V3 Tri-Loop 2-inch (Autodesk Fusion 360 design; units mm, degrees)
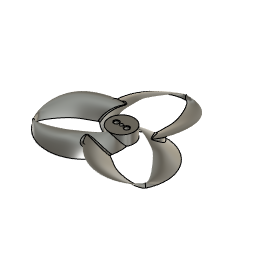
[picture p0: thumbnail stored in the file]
work_plane "WorkPlane9" AlongDistance 2.5
work_plane "WorkPlane10" AlongDistance -2.5
coil_primitive "CoilPrimitive4" Diameter 12 SectionSize 1 TaperAngle 0 Height 38.1 (= "( 25.4 * 1.5 ) * 1 mm")
coil_primitive "CoilPrimitive5" Diameter 25.4 SectionSize 1 TaperAngle 0 Height 38.1 (= "( 25.4 * 1.5 ) * 1 mm")
move "Move1"
sketch "Profile Start" plane through (2.5, 0, 0) normal (1, 0, 0) x axis (0, 1, 0)
  line L1 (-2.2, 0) -> (-3, 0)
  curve K1 (-3, 0) -> (-2.2, 0)
  curve K2 (-4, -1.5) -> (-2, 1.5)
  curve K3 (-1.2, 1.5) -> (-3.2, -1.5)
  curve K4 (1.75, 5) -> (2.25, 5)
  point P2 (-3, 0)
  point P4 (-2.2, 0)
  point P3 (2, 5)
  point P1 (0, 0)
  point P5 (-2, 1.5)
  point P8 (-1.2, 1.5)
  point P9 (2.25, 5)
  point P10 (1.75, 5)
  horizontal L1
  midpoint P2 K2
  midpoint P4 K3
  midpoint P3 K4
  dimension "d65" distance P1 P3 = 2
  dimension "d66" distance P1 P3 = 5
  dimension "d67" distance P1 P2 = 3
  dimension "d68" distance P2 P5 = 1
  dimension "d69" distance P2 P5 = 1.5
  dimension "d70" distance P4 P8 = 1.5
  dimension "d71" distance P5 P8 = 0.8
  dimension "d72" distance P9 P10 = 0.5
  dimension "d134" distance P2 P4 = 0.8
sketch "Profile End" plane through (-2.5, 0, 0) normal (1, 0, 0) x axis (0, 1, 0)
  curve K1 (3, 0) -> (2.2, 0)
  curve K2 (1.5, 1.5) -> (3.3196, -1.2262)
  curve K3 (-1.75, 4.6) -> (-2.25, 4.6)
  curve K4 (4, -1.5) -> (2, 1.5)
  line L1 (-1.75, 4.6) -> (-2.25, 4.6)
  line L2 (2.2, 0) -> (3, 0)
  point P5 (-1.75, 4.6)
  point P9 (-2.25, 4.6)
  point P4 (2.2, 0)
  point P8 (3, 0)
  point P6 (-2, 4.5)
  point P11 (0, 0)
  point P3 (1.5, 1.5)
  point P7 (2, 1.5)
  dimension "d84" distance P5 P9 = 0.5
  dimension "d89" distance P4 P8 = 0.8
  dimension "d101" distance P6 P11 = 4.5
  dimension "d102" distance P6 P11 = 2
  dimension "d103" distance P8 P11 = 3
  dimension "d104" distance P3 P11 = 1.5
  dimension "d105" distance P3 P11 = 1.5
  dimension "d106" distance P7 P11 = 2
  dimension "d107" distance P7 P11 = 1.5
sketch "Target Shape" plane through (0, 0, 0) normal (0, 0, 1) x axis (1, 0, 0)
  circle C1 centre (0, 0) radius 25.4
  circle C2 centre (0, 11.7) radius 13.7
  point P1 (0, 0)
  point P2 (0, 0)
  coincident P1 P2
  tangent C1 C2
  dimension "d95" diameter C1 = 50.8
sketch "Profile Edge" plane through (0, 0, 0) normal (1, 0, 0) x axis (0, 1, 0)
  line L1 (25.4, 0) -> (24.9, 0)
  curve K1 (24.9, 0) -> (25.4, 0)
  curve K2 (25.0501, 1.9961) -> (25.2499, 2.0039)
  curve K3 (25.4, 0.8) -> (25.4, -0.8)
  curve K4 (24.9, -0.8) -> (24.9, 0.8)
  point P4 (25.15, 2)
  point P3 (25.4, 0)
  point P2 (24.9, 0)
  point P1 (0, 0)
  point P5 (25.2499, 2.0039)
  point P6 (25.0501, 1.9961)
  horizontal L1
  midpoint P4 K2
  midpoint P3 K3
  midpoint P2 K4
  dimension "d96" distance P2 P3 = 0.5
  dimension "d98" distance P3 P4 = 2
  dimension "d121" distance P1 P4 = 2
  dimension "d138" distance P5 P6 = 0.2
work_plane "WorkPlane11" AlongDistance 12.7 (= "( 50.8 / 4 ) * 1 mm")
sketch "Profile Mid" plane through (0, 12.7, 0) normal (0, 1, 0) x axis (1, 0, 0)
  line L1 (12.7, 0) -> (13.5, 0)
  curve K1 (12.7, 0) -> (13.5, 0)
  curve K2 (5.25, -4.5) -> (5.75, -4.5)
  curve K3 (14.4, 1.5) -> (11, -1.5)
  curve K4 (11.8, -1.5) -> (15.2, 1.5)
  line L2 (-6.3, 0) -> (-5.5, 0)
  curve K5 (-6.3, 0) -> (-5.5, 0)
  curve K6 (-7.3, -1.5) -> (-3.7, 1.5)
  curve K7 (-13.7, -4.5) -> (-13.3, -4.5)
  curve K8 (-4.3, 1.5) -> (-8.3, -1.5)
  point P3 (5.5, -4.5)
  point P4 (12.7, 0)
  point P2 (13.5, 0)
  point P15 (-13.5, -4.5)
  point P14 (-6.3, 0)
  point P11 (-5.5, 0)
  point P5 (5.75, -4.5)
  point P6 (5.25, -4.5)
  point P1 (0, 0)
  point P18 (-13.7, -4.5)
  point P19 (-13.3, -4.5)
  midpoint P3 K2
  midpoint P4 K3
  midpoint P2 K4
  midpoint P15 K7
  midpoint P14 K8
  midpoint P11 K6
  dimension "d109" distance P2 P4 = 0.8
  dimension "d110" distance P2 P3 = 4.5
  dimension "d111" distance P2 P3 = 8
  dimension "d112" distance P5 P6 = 0.5
  dimension "d113" distance P1 P2 = 13.5
  dimension "d114" distance P11 P14 = 0.8
  dimension "d116" distance P11 P15 = 8
  dimension "d117" distance P18 P19 = 0.4
  dimension "d118" distance P1 P15 = 13.5
  dimension "d187" distance P1 P15 = 4.5
sketch "Lower Rails" plane through (0, 0, 0) normal (0, 0, 1) x axis (1, 0, 0)
  curve K1 (-2.5, 2.2) -> (0, 25.4)
  curve K2 (1, 2) -> (-6, 2.4)
  curve K3 (-6.5029, 7.8529) -> (-6.0971, 17.5471)
  curve K4 (-1.5, 25.4) -> (1.5, 25.4)
  curve K5 (-2.5, 3) -> (0, 24.9)
  curve K6 (1.0379, 2.7978) -> (-6.0379, 3.2022)
  curve K7 (-5.4941, 9.0775) -> (-5.5059, 16.3225)
  curve K8 (-1.5, 24.9) -> (1.5, 24.9)
  arc A1 centre (-1.0067, 11.1418) radius 13.795 clockwise from (0, 24.9) to (2.5, -2.2)
  arc A2 centre (-0.805, 11.0191) radius 14.4034 clockwise from (0, 25.4) to (2.5, -3)
  point P8 (12.7, 12.7)
  point P9 (-6.3, 12.7)
  point P12 (-6.3, 12.7)
  point P10 (-2.5, 2.2)
  point P13 (-2.5, 2.2)
  point P11 (0, 25.4)
  point P5 (0, 24.9)
  point P20 (0, 24.9)
  point P21 (-5.5, 12.7)
  point P23 (-5.5, 12.7)
  point P4 (-2.5, 3)
  point P22 (-2.5, 3)
  point P33 (13.5, 12.7)
  point P30 (0, 25.4)
  point P28 (1.5, 24.9)
  point P29 (-1.5, 24.9)
  point P18 (1.5, 25.4)
  point P19 (-1.5, 25.4)
  coincident P8 A1
  coincident P9 P12
  coincident P10 P13
  midpoint P13 K2
  midpoint P12 K3
  midpoint P11 K4
  coincident P5 P20
  coincident P21 P23
  coincident P4 P22
  midpoint P22 K6
  parallel K2 K6
  midpoint P21 K7
  midpoint P20 K8
  coincident P33 A2
  coincident P11 P30
  dimension "d136" distance P28 P29 = 3
  dimension "d137" distance P18 P19 = 3
work_plane "WorkPlane12" AlongDistance 5
sketch "Upper Rails" plane through (0, 0, 5) normal (0, 0, 1) x axis (1, 0, 0)
  line L1 (0, 25.4) -> (0, 24.9)
  curve K1 (2.5, 2) -> (0, 25.15)
  curve K2 (-0.2, 2) -> (5.2, 2)
  curve K3 (5.51, 10.575) -> (5.4914, 14.825)
  curve K4 (1.5, 25.15) -> (-1.5, 25.15)
  curve K5 (-2.5, -2) -> (0, 25.15)
  curve K6 (3, -2) -> (-8, -2)
  curve K7 (-5, 25.15) -> (5, 25.15)
  curve K8 (-13.6414, 7.825) -> (-13.36, 17.575)
  point P7 (2.5, 2)
  point P9 (2.5, 2)
  point P6 (5.5007, 12.7)
  point P5 (0, 25.15)
  point P18 (-2.5, -2)
  point P16 (0, 25.15)
  point P17 (-13.5007, 12.7)
  point P14 (-1.5, 25.15)
  point P15 (1.5, 25.15)
  coincident P7 P9
  midpoint P7 K2
  midpoint P6 K3
  midpoint P5 K4
  midpoint P18 K6
  midpoint P16 K7
  midpoint P17 K8
  dimension "d135" distance P14 P15 = 3
loft "Loft3" sketch "Profile Start" + "Profile Mid" + "Profile Edge" bodies "Blade Template 2x1.6x3"
loft "Loft4" sketch "Profile Edge" + "Profile Mid" + "Profile End"
circular_pattern "C-Pattern2" TotalAngle 360
combine "Combine2" bodies "Blade Template 2x2.5x3 (1)"
offset_faces "OffsetFaces5" distance -0.5
circular_pattern "C-Pattern3" TotalAngle 360
combine "Combine3"
fillet "Fillet2" radius 1
copy_paste_bodies "CopyPasteBodies6"
move "Move2"
scale "Scale2" ScaleX 1.25 ScaleY 1.25
sketch "Hub 5mm T-Mount" plane through (0, 0, 0) normal (0, 0, 1) x axis (1, 0, 0)
  circle C1 centre (0, 0) radius 6
  circle C2 centre (0, 0) radius 0.8
  circle C3 centre (2.5, 0) radius 1.05
  circle C4 centre (-2.5, 0) radius 1.05
  point P1 (0, 0)
  point P2 (0, 0)
  point P3 (0, 0)
  point P5 (-2.5, 0)
  point P4 (2.5, 0)
  coincident P1 P2
  concentric C1 C2
  dimension "d150" diameter C1 = 12
  dimension "d151" diameter C2 = 1.6
  dimension "d152" diameter C3 = 2.1
  dimension "d153" diameter C4 = 2.1
  dimension "d154" distance P3 P5 = 2.5
  dimension "d155" distance P3 P4 = 2.5
extrude "Extrude4" new body sketch "Hub 5mm T-Mount" along normal blind 5 bodies "Hub 5mm T-Mount"
chamfer "Chamfer2" distance 0.25
chamfer "Chamfer6" distance 0.25
copy_paste_bodies "CopyPasteBodies7"
copy_paste_bodies "CopyPasteBodies8"
combine "Combine8"
mirror "Mirror5" mirrorStitchTolerance 0.1 bodies "2x1.6x3 CW"
combine "Combine9"
mirror "Mirror6" mirrorStitchTolerance 0.1 bodies "2.5x1.5x3 CW"
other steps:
base_feature "Base Feature6" bodies "Blade Template 2x1.6x3", "Blade Template 2.5x1.6x3"
base_feature "Base Feature7" bodies "Hub 5mm T-Mount", "2x1.6x3 CCW"
base_feature "Base Feature8" bodies "2x1.6x3 CCW", "2.5x1.5x3 CCW"
named bodies: "Blade Template 2x1.6x3", "Hub 5mm T-Mount", "Blade Template 2x2.5x3 (1)", "Blade Template 2.5x1.6x3", "2x1.6x3 CCW", "2.5x1.5x3 CCW", "2x1.6x3 CW", "2.5x1.5x3 CW"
